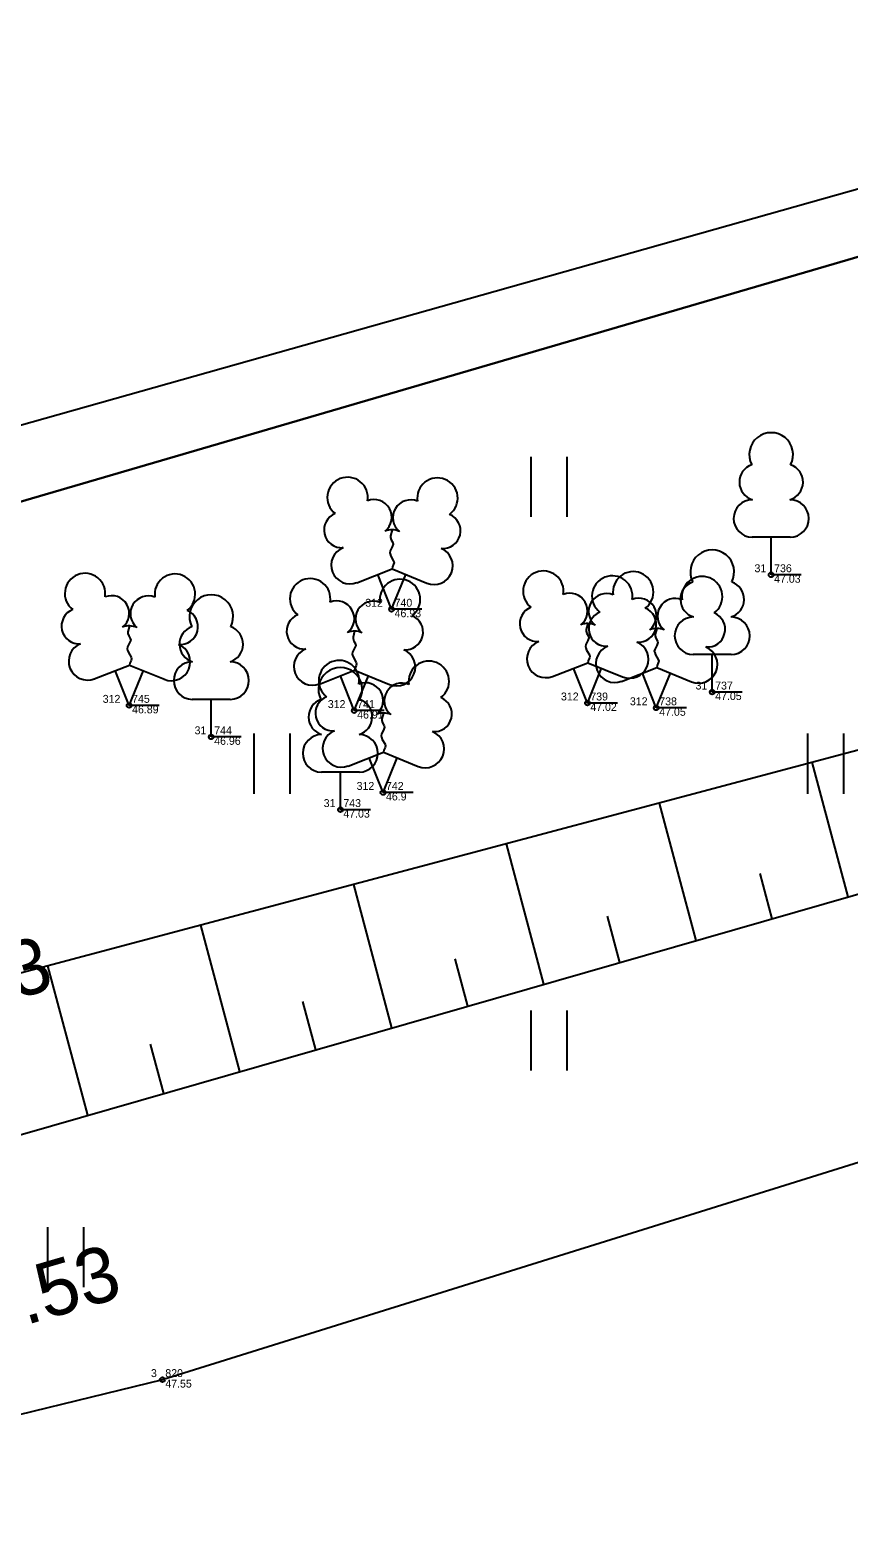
# Model space of a CAD drawing. Extents: x 543497 to 552146, y 6567125 to 6579845.
# Drawn here: x 545930.45 to 545940.79, y 6577662.71 to 6577681.77 of the extents above; entities that cross this region are included whole.
import ezdxf

# ---------------------------------------------------------------- set-up
doc = ezdxf.new("R2010")
doc.units = 0
for name, color, linetype in [('xref_Kangru tee 1_geodeesia$0$ABIJOONIS', 7, 'Continuous'), ('xref_Kangru tee 1_geodeesia$0$HALJASTUS', 7, 'Continuous'), ('xref_Kangru tee 1_geodeesia$0$mootkood', 7, 'Continuous'), ('xref_Kangru tee 1_geodeesia$0$MOOTKORG-eh2000', 7, 'Continuous'), ('xref_Kangru tee 1_geodeesia$0$mootmpunkt', 7, 'Continuous'), ('xref_Kangru tee 1_geodeesia$0$MOOTNR', 7, 'Continuous'), ('xref_Kangru tee 1_geodeesia$0$MOOTPIIR', 7, 'Continuous'), ('xref_Kangru tee 1_geodeesia$0$PIIR', 7, 'Continuous'), ('xref_Kangru tee 1_geodeesia$0$PUU', 7, 'Continuous'), ('xref_Kangru tee 1_geodeesia$0$RELJEEF', 7, 'Continuous'), ('xref_Kangru tee 1_geodeesia$0$TEE', 7, 'Continuous')]:
    doc.layers.add(name, color=color, linetype=linetype)

# ---------------------------------------------------------------- blocks, each defined once
blk = doc.blocks.new('xref_Kangru tee 1_geodeesia$0$LEHTP1')
for p, q in [((0.48, 0.95), (-0.48, 0.95)), ((0, 0), (0, 0.95)), ((0.76, 0), (0, 0))]:
    blk.add_line(p, q)
for centre, radius, start, end in [((0, 3.04), 0.554, 332.5799, 207.4201), ((-0.34, 2.345), 0.465, 109.0217, 253.1415), ((0.34, 2.345), 0.465, 286.8508, 70.9859), ((-0.475, 1.425), 0.475, 90.0016, 269.3953), ((0.475, 1.425), 0.475, 270.6047, 89.9984)]:
    blk.add_arc(centre, radius, start, end)
blk = doc.blocks.new('xref_Kangru tee 1_geodeesia$0$LEHTP2')
for p, q in [((-0.88, 0.67), (0.01, 1.02)), ((0, 0), (-0.35, 0.88)), ((0, 0), (0.36, 0.88)), ((0.01, 1.02), (0.89, 0.66)), ((0.76, 0), (0, 0))]:
    blk.add_line(p, q)
blk.add_lwpolyline([(0.01, 2.01), (-0.03, 1.86), (-0.03, 1.82), (-0.01, 1.76), (0.03, 1.69), (0.04, 1.65), (0.01, 1.58), (-0.04, 1.48), (-0.05, 1.43), (-0.04, 1.4), (-0.02, 1.34), (0.05, 1.22), (0.06, 1.18), (0.05, 1.14), (0.02, 1.07), (0.01, 1.02)])
for centre, radius, start, end in [((-1.114, 2.828), 0.512, 111.5027, 232.5173), ((-1.114, 2.828), 0.512, 350.4856, 111.5002), ((1.158, 2.811), 0.512, 67.6168, 188.6314), ((1.158, 2.811), 0.512, 306.5997, 67.6143), ((-0.445, 2.327), 0.448, 308.5041, 111.5725), ((0.481, 2.318), 0.45, 67.7016, 230.5126), ((-1.262, 2.005), 0.448, 111.4304, 274.4987), ((1.293, 1.986), 0.448, 264.6183, 67.6866), ((0.008, 1.535), 0.475, 66.7655, 111.5015), ((-1.053, 1.117), 0.475, 111.5014, 291.5004), ((1.07, 1.101), 0.475, 247.6166, 67.6155)]:
    blk.add_arc(centre, radius, start, end)
blk = doc.blocks.new('xref_Kangru tee 1_geodeesia$0$hein')
for p, q in [((-0.455, 0.761), (-0.455, -0.761)), ((0.455, 0.761), (0.455, -0.761))]:
    blk.add_line(p, q)

msp = doc.modelspace()

# ---------------------------------------------------------------- linework, layer by layer
at = {"layer": 'xref_Kangru tee 1_geodeesia$0$mootmpunkt'}
for centre in [(545939.812, 6577674.887), (545935.015, 6577674.451), (545931.697, 6577673.236), (545937.489, 6577673.266), (545939.067, 6577673.404), (545934.542, 6577673.17), (545938.36, 6577673.205), (545932.735, 6577672.838), (545934.906, 6577672.135), (545934.367, 6577671.918), (545932.117, 6577664.712)]:
    msp.add_circle(centre, 0.03, dxfattribs=at)
at = {"layer": 'xref_Kangru tee 1_geodeesia$0$MOOTPIIR'}
msp.add_lwpolyline([(545946.849, 6577681.441), (545929.256, 6577676.475), (545922.884, 6577675.308), (545920.417, 6577673.083), (545918.879, 6577673.245), (545918.49, 6577673.095), (545915.014, 6577671.398), (545914.071, 6577671.246), (545912.545, 6577670.135), (545910.571, 6577669.508), (545908.59, 6577668.894), (545905.466, 6577667.765), (545904.226, 6577667.219), (545895.757, 6577665.443), (545899.548, 6577655.166)], dxfattribs=at)
at = {"layer": 'xref_Kangru tee 1_geodeesia$0$PIIR'}
for points in [[(545872.69, 6577782.96), (545871.05, 6577786.39), (545874.7, 6577788.05), (545922.19, 6577809.68), (545973.61, 6577832.94), (545956.36, 6577869.23), (545939.5, 6577905.43), (546028.71, 6577946.4), (546081.11, 6577806.12), (545983.53, 6577775.51), (545969.55, 6577687.28), (545921.7, 6577673.29), (545918.84, 6577672.45), (545911.34, 6577697.47), (545909.71, 6577702.91), (545909.43, 6577705.29), (545905.92, 6577713.46), (545874.41, 6577779.36), (545872.69, 6577782.96)], [(545526.72, 6577483.94), (545567.61, 6577503.92), (545600.27, 6577519.26), (545639.76, 6577537.43), (545673.8, 6577552.72), (545712.72, 6577569.73), (545743.83, 6577582.87), (545764.02, 6577591.24), (545805.47, 6577607.21), (545907.89, 6577644.25), (545925.88, 6577650.4), (545918.84, 6577672.45), (545921.7, 6577673.29), (545969.55, 6577687.28), (546110.26, 6577728.46), (546113.86, 6577718.6), (546117.94, 6577707.48), (546328.8, 6577761.79)]]:
    msp.add_lwpolyline(points, dxfattribs=at)
at = {"layer": 'xref_Kangru tee 1_geodeesia$0$RELJEEF'}
for p, q in [((545940.784, 6577670.816), (545940.331, 6577672.517)), ((545938.862, 6577670.264), (545938.399, 6577672.002)), ((545936.94, 6577669.711), (545936.467, 6577671.487)), ((545935.018, 6577669.159), (545934.535, 6577670.973)), ((545939.823, 6577670.54), (545939.671, 6577671.113)), ((545933.095, 6577668.607), (545932.602, 6577670.458)), ((545937.901, 6577669.987), (545937.745, 6577670.573)), ((545935.979, 6577669.435), (545935.819, 6577670.034)), ((545931.173, 6577668.055), (545930.67, 6577669.943)), ((545934.056, 6577668.883), (545933.894, 6577669.494)), ((545932.134, 6577668.331), (545931.968, 6577668.954))]:
    msp.add_line(p, q, dxfattribs=at)
for points in [[(545919.143, 6577665.68), (545920.848, 6577664.88), (545923.697, 6577664.737), (545923.815, 6577665.608), (545925.282, 6577665.923), (545927.692, 6577667.055), (545947.623, 6577672.78), (545958.409, 6577677.256)], [(545958.409, 6577677.256), (545947.699, 6577674.479), (545927.03, 6577668.974), (545923.922, 6577667.621), (545921.922, 6577667.571)]]:
    msp.add_lwpolyline(points, dxfattribs=at)
at = {"layer": 'xref_Kangru tee 1_geodeesia$0$TEE'}
msp.add_lwpolyline([(546059.977, 6577715.174), (546061.866, 6577715.362), (546062.121, 6577710.624), (546061.045, 6577709.272), (546060.882, 6577708.001), (546060.893, 6577706.804), (546060.369, 6577705.849), (546059.158, 6577705.188), (546056.387, 6577704.301), (546050.232, 6577703.156), (546045.314, 6577701.613), (546044.543, 6577701.325), (546040.274, 6577700.368), (546017.855, 6577692.963), (545995.651, 6577685.598), (545969.99, 6577676.752), (545949.859, 6577670.253), (545932.117, 6577664.712), (545929.387, 6577664.046), (545924.424, 6577663.904), (545920.826, 6577664.534), (545918.964, 6577665.384), (545916.564, 6577667.08), (545914.824, 6577669.08)], dxfattribs=at)

# ---------------------------------------------------------------- block references
at = {"layer": 'xref_Kangru tee 1_geodeesia$0$HALJASTUS', "xscale": 0.5, "yscale": 0.5}
for p in [(545937, 6577676), (545933.5, 6577672.5), (545940.5, 6577672.5), (545937, 6577669), (545930.892, 6577666.26)]:
    msp.add_blockref('xref_Kangru tee 1_geodeesia$0$hein', p, dxfattribs=at)
at = {"layer": 'xref_Kangru tee 1_geodeesia$0$PUU', "xscale": 0.5, "yscale": 0.5}
for name, p in [('xref_Kangru tee 1_geodeesia$0$LEHTP1', (545939.812, 6577674.887)), ('xref_Kangru tee 1_geodeesia$0$LEHTP2', (545935.015, 6577674.451)), ('xref_Kangru tee 1_geodeesia$0$LEHTP1', (545939.067, 6577673.404)), ('xref_Kangru tee 1_geodeesia$0$LEHTP2', (545931.697, 6577673.236)), ('xref_Kangru tee 1_geodeesia$0$LEHTP2', (545934.542, 6577673.17)), ('xref_Kangru tee 1_geodeesia$0$LEHTP2', (545937.489, 6577673.266)), ('xref_Kangru tee 1_geodeesia$0$LEHTP2', (545938.36, 6577673.205)), ('xref_Kangru tee 1_geodeesia$0$LEHTP1', (545932.735, 6577672.838)), ('xref_Kangru tee 1_geodeesia$0$LEHTP2', (545934.906, 6577672.135)), ('xref_Kangru tee 1_geodeesia$0$LEHTP1', (545934.367, 6577671.918))]:
    msp.add_blockref(name, p, dxfattribs=at)

# ---------------------------------------------------------------- texts
at = {"layer": 'xref_Kangru tee 1_geodeesia$0$ABIJOONIS'}
for s, rotation, p in [('h=2.93', 16.3313, (545927.999, 6577668.855)), ('h=4.53', 16.3152, (545928.865, 6577664.954))]:
    msp.add_text(s, height=0.7, rotation=rotation, dxfattribs=at).set_placement(p)
at = {"layer": 'xref_Kangru tee 1_geodeesia$0$mootkood'}
for s, p in [(' 31', (545939.564, 6577674.92)), (' 312', (545934.644, 6577674.484)), (' 31', (545938.819, 6577673.437)), (' 312', (545931.326, 6577673.269)), (' 312', (545934.171, 6577673.203)), (' 312', (545937.118, 6577673.299)), (' 312', (545937.989, 6577673.238)), (' 31', (545932.487, 6577672.871)), (' 312', (545934.535, 6577672.168)), (' 31', (545934.119, 6577671.951)), (' 3', (545931.936, 6577664.745))]:
    msp.add_text(s, height=0.1, dxfattribs=at).set_placement(p)
at = {"layer": 'xref_Kangru tee 1_geodeesia$0$MOOTKORG-eh2000'}
for s, p in [(' 47.03', (545939.812, 6577674.787)), (' 46.93', (545935.015, 6577674.351)), (' 47.02', (545937.489, 6577673.166)), (' 47.05', (545939.067, 6577673.304)), (' 46.89', (545931.697, 6577673.136)), (' 46.91', (545934.542, 6577673.07)), (' 47.05', (545938.36, 6577673.105)), (' 46.96', (545932.735, 6577672.738)), (' 46.9', (545934.906, 6577672.035)), (' 47.03', (545934.367, 6577671.818)), (' 47.55', (545932.117, 6577664.612))]:
    msp.add_text(s, height=0.1, dxfattribs=at).set_placement(p)
at = {"layer": 'xref_Kangru tee 1_geodeesia$0$MOOTNR'}
for s, p in [(' 736', (545939.812, 6577674.92)), (' 740', (545935.015, 6577674.484)), (' 737', (545939.067, 6577673.437)), (' 745', (545931.697, 6577673.269)), (' 741', (545934.542, 6577673.203)), (' 739', (545937.489, 6577673.299)), (' 738', (545938.36, 6577673.238)), (' 744', (545932.735, 6577672.871)), (' 742', (545934.906, 6577672.168)), (' 743', (545934.367, 6577671.951)), (' 820', (545932.117, 6577664.745))]:
    msp.add_text(s, height=0.1, dxfattribs=at).set_placement(p)

doc.saveas('drawing.dxf')
